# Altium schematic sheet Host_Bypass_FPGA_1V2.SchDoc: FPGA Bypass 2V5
size A4; Organization: Altium Limited.; Address1: Level 3, 12a Rodborough Rd; Address2: Frenchs Forest 2086; Address3: NSW; Address4: AUSTRALIA; DocumentNumber: 26; SheetNumber: 27; SheetTotal: 77; PageSetup: Record=PageOptions|CenterHorizontal=True|CenterVertical=True|PrintScale=0.97|XCorrection=1.00|YCorrection=1.00|PrintKind=0|BorderSize=5000000|LeftOffset=0|BottomOffset=0|Orientation=2|PaperLength=1000|PaperWidth=1000|Scale=100|PaperSource=7|PrintQuality=-4|MediaType=1|DitherType=10|PaperKind=A4 (210 x 297 mm)|PrintScaleMode=1
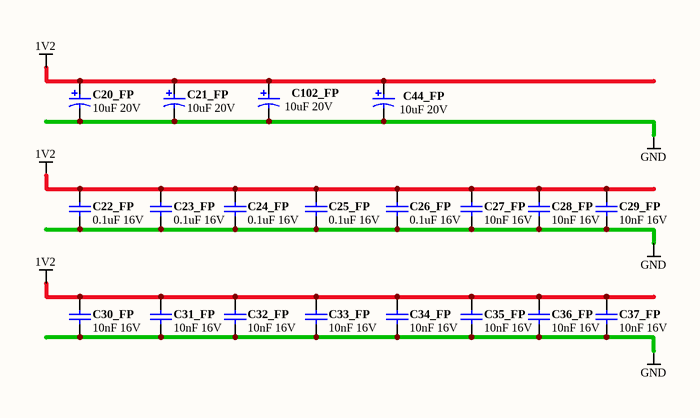
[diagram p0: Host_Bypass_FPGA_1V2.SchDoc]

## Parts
C20_FP  10uF 20V  [CAPC3528-STAR]
C21_FP  10uF 20V  [CAPC3528-STAR]
C22_FP  0.1uF 16V  [CAPC1005-STAR]
C23_FP  0.1uF 16V  [CAPC1005-STAR]
C24_FP  0.1uF 16V  [CAPC1005-STAR]
C25_FP  0.1uF 16V  [CAPC1005-STAR]
C26_FP  0.1uF 16V  [CAPC1005-STAR]
C27_FP  10nF 16V  [CAPC1005-STAR]
C28_FP  10nF 16V  [CAPC1005-STAR]
C29_FP  10nF 16V  [CAPC1005-STAR]
C30_FP  10nF 16V  [CAPC1005-STAR]
C31_FP  10nF 16V  [CAPC1005-STAR]
C32_FP  10nF 16V  [CAPC1005-STAR]
C33_FP  10nF 16V  [CAPC1005-STAR]
C34_FP  10nF 16V  [CAPC1005-STAR]
C35_FP  10nF 16V  [CAPC1005-STAR]
C36_FP  10nF 16V  [CAPC1005-STAR]
C37_FP  10nF 16V  [CAPC1005-STAR]
C44_FP  10uF 20V  [CAPC3528-STAR]
C102_FP  10uF 20V  [CAPC3528-STAR]

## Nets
1V2: C20_FP.1 C21_FP.1 C22_FP.1 C23_FP.1 C24_FP.1 C25_FP.1 C26_FP.1 C27_FP.1 C28_FP.1 C29_FP.1 C30_FP.1 C31_FP.1 C32_FP.1 C33_FP.1 C34_FP.1 C35_FP.1 C36_FP.1 C37_FP.1 C44_FP.1 C102_FP.1
GND: C20_FP.2 C21_FP.2 C22_FP.2 C23_FP.2 C24_FP.2 C25_FP.2 C26_FP.2 C27_FP.2 C28_FP.2 C29_FP.2 C30_FP.2 C31_FP.2 C32_FP.2 C33_FP.2 C34_FP.2 C35_FP.2 C36_FP.2 C37_FP.2 C44_FP.2 C102_FP.2

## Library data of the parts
C20_FP C21_FP C44_FP C102_FP = D-101-0007: Capacitor, Tantalum, 10uF 10% 20V MCCT-B (3528); Polarity: Polarized
C22_FP C23_FP C24_FP C25_FP C26_FP = D-101-0080: Capacitor, Ceramic, 0.1uF 10% 16V 0402 (1005) X7R; Polarity: Non-Polarized
C27_FP C28_FP C29_FP C30_FP C31_FP C32_FP C33_FP C34_FP C35_FP C36_FP C37_FP = D-101-0077: Capacitor, Ceramic, 10nF 10% 16V 0402 (1005) X7R; Polarity: Non-Polarized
